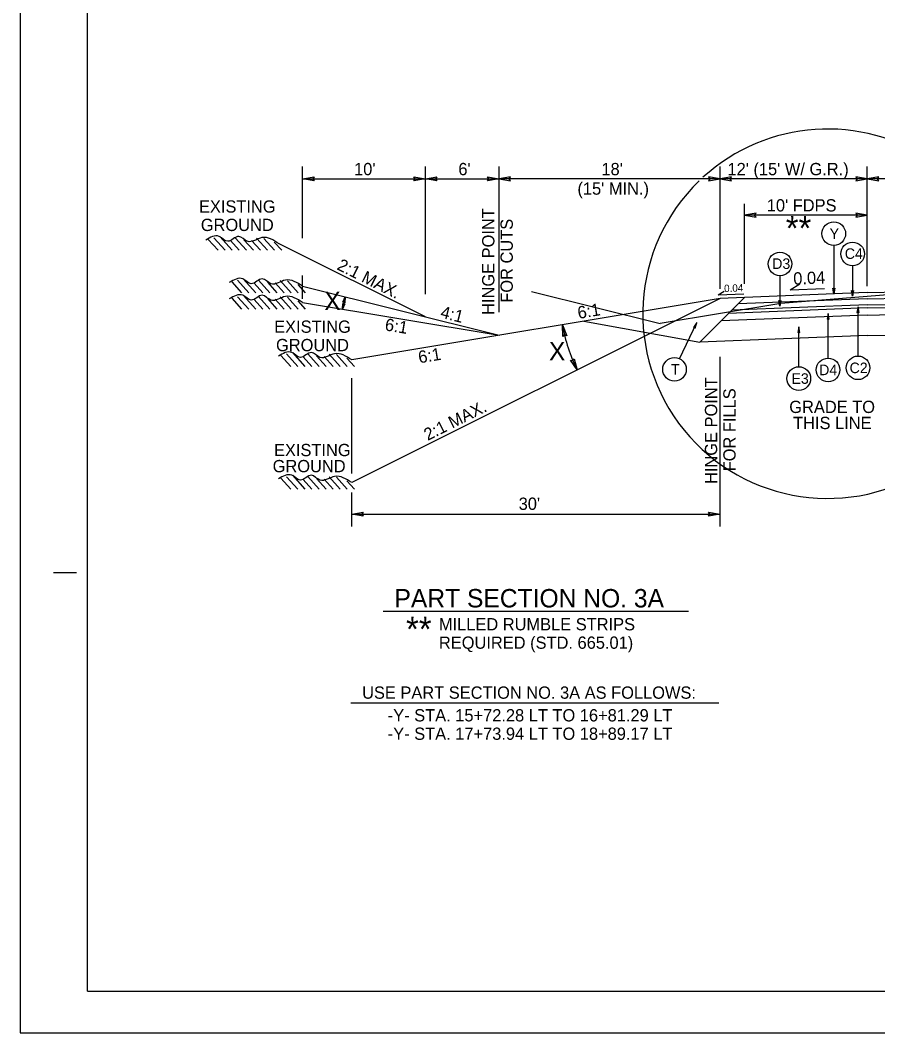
# Model space of a CAD drawing. Extents: x 1553884 to 1554215, y 810431 to 810779.
# Drawn here: x 1553901.4 to 1553971.2, y 810431 to 810513.5 of the extents above; entities that cross this region are included whole.
import ezdxf

# ---------------------------------------------------------------- set-up
doc = ezdxf.new("R2010")
doc.units = 0
for name, color, linetype in [('Old_Level_1', 7, 'Continuous'), ('Old_Level_15', 7, 'Continuous'), ('Old_Level_2', 7, 'Continuous'), ('Old_Level_20', 7, 'Continuous'), ('Prop Lane Arrow CELL', 7, 'Continuous'), ('Prop Shade Light', 7, 'Continuous'), ('Scratch_Level_0', 7, 'Continuous'), ('Sheet Plot Border Inside CELL', 7, 'Continuous'), ('Typical Arrow Superelevation CELL', 7, 'Continuous'), ('Typical Detail Pavement Repair CELL', 7, 'Continuous'), ('Typical Shoulder Slope CELL', 7, 'Continuous'), ('Typical Text ID Circle CELL', 7, 'Continuous')]:
    doc.layers.add(name, color=color, linetype=linetype)

msp = doc.modelspace()

# ---------------------------------------------------------------- linework, layer by layer
at = {"layer": 'Old_Level_1'}
for start, end in [(55.3594, 132.39727), (133.99022, 29.28511)]:
    msp.add_arc((1553967.115, 810489.54), 15.049, start, end, dxfattribs=at)
at = {"layer": 'Old_Level_15'}
for points in [[(1553925.295, 810500.365), (1553924.357, 810500.526), (1553925.3, 810500.693), (1553925.18, 810500.526)], [(1553933.42, 810500.688), (1553934.357, 810500.526), (1553933.415, 810500.36), (1553933.535, 810500.526)], [(1553935.295, 810500.365), (1553934.357, 810500.526), (1553935.3, 810500.693), (1553935.18, 810500.526)], [(1553939.42, 810500.688), (1553940.357, 810500.526), (1553939.415, 810500.36), (1553939.535, 810500.526)], [(1553941.295, 810500.688), (1553940.357, 810500.526), (1553941.3, 810500.36), (1553941.18, 810500.526)], [(1553957.42, 810500.365), (1553958.357, 810500.526), (1553957.415, 810500.693), (1553957.535, 810500.526)], [(1553959.295, 810500.688), (1553958.357, 810500.526), (1553959.3, 810500.36), (1553959.18, 810500.526)], [(1553969.42, 810500.365), (1553970.357, 810500.526), (1553969.415, 810500.693), (1553969.535, 810500.526)], [(1553971.295, 810500.688), (1553970.357, 810500.526), (1553971.3, 810500.36), (1553971.18, 810500.526)], [(1553961.295, 810497.732), (1553960.357, 810497.571), (1553961.3, 810497.404), (1553961.18, 810497.571)], [(1553969.42, 810497.409), (1553970.357, 810497.571), (1553969.415, 810497.737), (1553969.535, 810497.571)], [(1553927.64, 810490.475), (1553927.827, 810490.913), (1553927.799, 810490.435), (1553927.732, 810490.512)], [(1553967.705, 810491.619), (1553967.624, 810491.151), (1553967.541, 810491.622), (1553967.624, 810491.562)], [(1553969.236, 810491.435), (1553969.156, 810490.967), (1553969.072, 810491.438), (1553969.156, 810491.378)], [(1553927.781, 810490.35), (1553927.617, 810489.903), (1553927.62, 810490.382), (1553927.691, 810490.308)], [(1553963.324, 810490.618), (1553963.243, 810490.149), (1553963.16, 810490.62), (1553963.243, 810490.56)], [(1553969.68, 810489.63), (1553969.6, 810490.099), (1553969.516, 810489.627), (1553969.6, 810489.687)], [(1553967.24, 810489.095), (1553967.16, 810489.563), (1553967.076, 810489.092), (1553967.16, 810489.152)], [(1553945.546, 810487.69), (1553945.52, 810488.64), (1553945.869, 810487.749), (1553945.682, 810487.834)], [(1553956.341, 810488.357), (1553956.471, 810488.815), (1553956.192, 810488.425), (1553956.293, 810488.443)], [(1553964.857, 810488.009), (1553964.776, 810488.477), (1553964.693, 810488.006), (1553964.776, 810488.066)], [(1553946.471, 810485.878), (1553946.717, 810484.96), (1553946.171, 810485.746), (1553946.372, 810485.707)], [(1553929.295, 810473.053), (1553928.357, 810473.214), (1553929.3, 810473.381), (1553929.18, 810473.214)], [(1553957.42, 810473.376), (1553958.357, 810473.214), (1553957.415, 810473.048), (1553957.535, 810473.214)]]:
    msp.add_lwpolyline(points, close=True, dxfattribs=at)
at = {"layer": 'Old_Level_2'}
for p, q in [((1553906.821, 810434.329), (1553906.825, 810592.576)), ((1553904.055, 810468.454), (1553905.93, 810468.452)), ((1553906.821, 810434.329), (1554154.321, 810434.329))]:
    msp.add_line(p, q, dxfattribs=at)
at = {"layer": 'Old_Level_20'}
for p, q in [((1553942.992, 810491.361), (1553953.484, 810488.738)), ((1553972.357, 810491.1), (1553963.311, 810490.376)), ((1553963.311, 810490.376), (1553953.484, 810488.738))]:
    msp.add_line(p, q, dxfattribs=at)
at = {"layer": 'Prop Lane Arrow CELL'}
for p, q in [((1553901.353, 810595.951), (1553901.353, 810430.954)), ((1553901.353, 810430.954), (1554156.35, 810430.954))]:
    msp.add_line(p, q, dxfattribs=at)
at = {"layer": 'Prop Shade Light'}
for p, q in [((1553960.357, 810490.86), (1553956.711, 810487.214)), ((1553970.357, 810491.26), (1553960.357, 810490.86)), ((1553970.357, 810491.26), (1553982.357, 810491.5)), ((1553970.357, 810490.76), (1553982.357, 810491)), ((1553970.357, 810490.26), (1553959.316, 810489.818)), ((1553970.357, 810490.76), (1553959.836, 810490.339)), ((1553970.357, 810490.26), (1553972.357, 810490.3)), ((1553970.357, 810490.01), (1553972.357, 810490.05)), ((1553970.357, 810489.427), (1553958.448, 810488.95)), ((1553970.357, 810490.01), (1553959.055, 810489.558)), ((1553970.357, 810489.427), (1553972.357, 810489.467)), ((1553970.357, 810487.76), (1553956.711, 810487.214)), ((1553970.357, 810487.76), (1553972.357, 810487.8))]:
    msp.add_line(p, q, dxfattribs=at)
at = {"layer": 'Scratch_Level_0'}
msp.add_line((1553901.353, 810430.954), (1553901.353, 810430.954), dxfattribs=at)
at = {"layer": 'Sheet Plot Border Inside CELL'}
for p, q in [((1553917.599, 810495.845), (1553918.621, 810494.709)), ((1553916.672, 810495.596), (1553917.469, 810494.709)), ((1553917.134, 810495.722), (1553918.045, 810494.709)), ((1553918.487, 810495.498), (1553919.197, 810494.709)), ((1553918.848, 810495.737), (1553919.773, 810494.709)), ((1553919.573, 810495.571), (1553920.349, 810494.709)), ((1553920.197, 810495.519), (1553920.925, 810494.709)), ((1553920.607, 810495.703), (1553921.501, 810494.709)), ((1553921.202, 810495.681), (1553922.077, 810494.709)), ((1553922.051, 810495.378), (1553922.653, 810494.709)), ((1553918.59, 810492.136), (1553919.388, 810491.25)), ((1553919.053, 810492.262), (1553919.964, 810491.25)), ((1553919.518, 810492.385), (1553920.54, 810491.25)), ((1553920.406, 810492.039), (1553921.116, 810491.25)), ((1553920.767, 810492.278), (1553921.692, 810491.25)), ((1553921.492, 810492.112), (1553922.268, 810491.25)), ((1553922.116, 810492.059), (1553922.844, 810491.25)), ((1553922.526, 810492.244), (1553923.42, 810491.25)), ((1553923.121, 810492.222), (1553923.996, 810491.25)), ((1553923.97, 810491.918), (1553924.572, 810491.25)), ((1553919.053, 810490.929), (1553919.964, 810489.916)), ((1553919.518, 810491.052), (1553920.54, 810489.916)), ((1553920.767, 810490.945), (1553921.692, 810489.916)), ((1553922.526, 810490.91), (1553923.42, 810489.916)), ((1553923.121, 810490.889), (1553923.996, 810489.916)), ((1553918.59, 810490.803), (1553919.388, 810489.916)), ((1553920.406, 810490.706), (1553921.116, 810489.916)), ((1553921.492, 810490.779), (1553922.268, 810489.916)), ((1553922.116, 810490.726), (1553922.844, 810489.916)), ((1553923.97, 810490.585), (1553924.572, 810489.916)), ((1553922.59, 810486.136), (1553923.388, 810485.25)), ((1553923.053, 810486.262), (1553923.964, 810485.25)), ((1553923.518, 810486.385), (1553924.54, 810485.25)), ((1553924.406, 810486.039), (1553925.116, 810485.25)), ((1553924.767, 810486.278), (1553925.692, 810485.25)), ((1553925.492, 810486.112), (1553926.268, 810485.25)), ((1553926.116, 810486.059), (1553926.844, 810485.25)), ((1553926.526, 810486.244), (1553927.42, 810485.25)), ((1553927.121, 810486.222), (1553927.996, 810485.25)), ((1553927.97, 810485.918), (1553928.572, 810485.25)), ((1553922.59, 810476.136), (1553923.388, 810475.25)), ((1553923.053, 810476.262), (1553923.964, 810475.25)), ((1553923.518, 810476.385), (1553924.54, 810475.25)), ((1553924.406, 810476.039), (1553925.116, 810475.25)), ((1553924.767, 810476.278), (1553925.692, 810475.25)), ((1553925.492, 810476.112), (1553926.268, 810475.25)), ((1553926.116, 810476.059), (1553926.844, 810475.25)), ((1553926.526, 810476.244), (1553927.42, 810475.25)), ((1553927.121, 810476.222), (1553927.996, 810475.25)), ((1553927.97, 810475.918), (1553928.572, 810475.25))]:
    msp.add_line(p, q, dxfattribs=at)
for points in [[(1553922.438, 810495.239), (1553921.044, 810495.738), (1553919.849, 810495.439), (1553919.152, 810495.838), (1553918.256, 810495.439), (1553917.558, 810495.838), (1553916.463, 810495.539)], [(1553924.357, 810491.78), (1553922.963, 810492.279), (1553921.768, 810491.979), (1553921.071, 810492.378), (1553920.175, 810491.979), (1553919.477, 810492.378), (1553918.382, 810492.079)], [(1553924.357, 810490.447), (1553922.963, 810490.945), (1553921.768, 810490.646), (1553921.071, 810491.045), (1553920.175, 810490.646), (1553919.477, 810491.045), (1553918.382, 810490.746)], [(1553928.357, 810485.78), (1553926.963, 810486.279), (1553925.768, 810485.979), (1553925.071, 810486.378), (1553924.175, 810485.979), (1553923.477, 810486.378), (1553922.382, 810486.079)], [(1553928.357, 810475.78), (1553926.963, 810476.279), (1553925.768, 810475.979), (1553925.071, 810476.378), (1553924.175, 810475.979), (1553923.477, 810476.378), (1553922.382, 810476.079)]]:
    msp.add_spline(points, degree=3, dxfattribs=at)
at = {"layer": 'Typical Arrow Superelevation CELL'}
for p, q in [((1553940.357, 810489.66), (1553940.357, 810501.526)), ((1553958.357, 810491.557), (1553958.357, 810501.526)), ((1553960.357, 810491.975), (1553960.357, 810498.485)), ((1553964.076, 810491.477), (1553964.85, 810491.966)), ((1553958.218, 810491.075), (1553958.682, 810491.368)), ((1553958.218, 810491.075), (1553960.288, 810491.157)), ((1553964.076, 810491.477), (1553966.871, 810491.589)), ((1553958.357, 810472.214), (1553958.357, 810486.035)), ((1553928.357, 810476.524), (1553928.357, 810484.301)), ((1553928.357, 810472.214), (1553928.357, 810474.97)), ((1553930.921, 810465.301), (1553955.794, 810465.301)), ((1553928.296, 810457.849), (1553958.255, 810457.849))]:
    msp.add_line(p, q, dxfattribs=at)
for centre, radius, start, end in [((1553940.357, 810487.78), 12.916, 165.96376, 170.53768), ((1553958.357, 810490.78), 13.014, 189.46232, 206.56505)]:
    msp.add_arc(centre, radius, start, end, dxfattribs=at)
at = {"layer": 'Typical Shoulder Slope CELL'}
for p, q in [((1553924.357, 810495.694), (1553924.357, 810501.526)), ((1553934.357, 810491.147), (1553934.357, 810501.526)), ((1553970.357, 810491.78), (1553970.357, 810501.526)), ((1553924.357, 810500.526), (1553934.357, 810500.526)), ((1553934.357, 810500.526), (1553940.357, 810500.526)), ((1553958.357, 810500.526), (1553940.357, 810500.526)), ((1553970.357, 810500.526), (1553958.357, 810500.526)), ((1553982.357, 810500.526), (1553970.357, 810500.526)), ((1553970.357, 810497.571), (1553960.357, 810497.571)), ((1553934.357, 810489.28), (1553922.438, 810495.239)), ((1553924.357, 810490.755), (1553924.357, 810492.646)), ((1553924.357, 810491.78), (1553940.357, 810487.78)), ((1553960.357, 810490.86), (1553958.357, 810490.78)), ((1553924.357, 810490.447), (1553940.357, 810487.78)), ((1553958.357, 810490.78), (1553928.357, 810485.78)), ((1553958.357, 810490.78), (1553928.357, 810475.78)), ((1553947.263, 810488.931), (1553956.711, 810487.214)), ((1553928.357, 810473.214), (1553958.357, 810473.214))]:
    msp.add_line(p, q, dxfattribs=at)
at = {"layer": 'Typical Text ID Circle CELL'}
for p, q in [((1553967.624, 810495.103), (1553967.624, 810491.151)), ((1553969.156, 810493.452), (1553969.156, 810490.967)), ((1553963.243, 810492.634), (1553963.243, 810490.149)), ((1553969.6, 810486.091), (1553969.6, 810490.099)), ((1553967.16, 810485.924), (1553967.16, 810489.563)), ((1553955.066, 810485.875), (1553956.471, 810488.815)), ((1553964.776, 810485.219), (1553964.776, 810488.477))]:
    msp.add_line(p, q, dxfattribs=at)
for centre in [(1553967.624, 810496.064), (1553969.156, 810494.413), (1553963.243, 810493.596), (1553954.651, 810485.007), (1553967.16, 810484.962), (1553969.6, 810485.13), (1553964.776, 810484.258)]:
    msp.add_circle(centre, 0.962, dxfattribs=at)

# ---------------------------------------------------------------- texts
at = {"layer": 'Typical Arrow Superelevation CELL'}
for s, height, p in [("10'", 1, (1553928.547, 810500.827)), ("6'", 1, (1553937.042, 810500.827)), ("18'", 1, (1553948.697, 810500.827)), ("12' (15' W/ G.R.)", 1, (1553958.966, 810500.827)), ("(15' MIN.)", 1, (1553946.743, 810499.239)), ('EXISTING', 1, (1553915.912, 810497.778)), ("10' FDPS", 1, (1553962.166, 810497.871)), ('**', 2, (1553963.715, 810495.508)), ('GROUND', 1, (1553916.061, 810496.278)), ('X', 1.5, (1553926.118, 810489.837)), ('EXISTING', 1, (1553922.039, 810487.986)), ('GROUND', 1, (1553922.188, 810486.486)), ('X', 1.5, (1553944.421, 810485.733)), ('GRADE TO ', 1, (1553963.999, 810481.45)), ('THIS LINE', 1, (1553964.311, 810480.139)), ('EXISTING', 1, (1553922.025, 810477.935)), ('GROUND', 1, (1553921.916, 810476.624)), ("30'", 1, (1553941.956, 810473.559)), ('PART SECTION NO. 3A', 1.5, (1553931.838, 810465.609)), ('**', 2, (1553932.779, 810462.843)), ('MILLED RUMBLE STRIPS', 1, (1553935.458, 810463.74)), ('REQUIRED (STD. 665.01)', 1, (1553935.458, 810462.24)), ('USE PART SECTION NO. 3A AS FOLLOWS:', 1, (1553929.202, 810458.169)), ('-Y- STA. 15+72.28 LT TO 16+81.29 LT', 1, (1553931.291, 810456.321)), ('-Y- STA. 17+73.94 LT TO 18+89.17 LT', 1, (1553931.291, 810454.821))]:
    msp.add_text(s, height=height, dxfattribs=at).set_placement(p)
for s, height, rotation, p in [('HINGE POINT', 1, 90, (1553939.978, 810489.445)), ('FOR CUTS', 1, 90, (1553941.478, 810490.438)), ('2:1 MAX.', 1, 333.43495, (1553927.079, 810493.184)), ('0.04', 1, 2.29061, (1553964.345, 810491.906)), ('0.04', 0.6, 2.29061, (1553958.702, 810491.299)), ('4:1', 1, 345.96376, (1553935.52, 810489.23)), ('6:1', 1, 9.46232, (1553946.835, 810489.116)), ('6:1', 1, 350.53768, (1553931.005, 810488.194)), ('6:1', 1, 9.46232, (1553933.862, 810485.494)), ('HINGE POINT', 1, 90, (1553958.127, 810475.666)), ('FOR FILLS', 1, 90, (1553959.627, 810476.698)), ('2:1 MAX.', 1, 26.56505, (1553934.544, 810479.168))]:
    msp.add_text(s, height=height, rotation=rotation, dxfattribs=at).set_placement(p)
at = {"layer": 'Typical Detail Pavement Repair CELL'}
for s, height, p in [('Y', 0.861, (1553967.287, 810495.634)), ('C4', 0.8608, (1553968.52, 810494.007)), ('D3', 0.8608, (1553962.609, 810493.189)), ('T', 0.861, (1553954.368, 810484.577)), ('D4', 0.8608, (1553966.433, 810484.532)), ('C2', 0.8608, (1553968.914, 810484.699)), ('E3', 0.8608, (1553964.18, 810483.827))]:
    msp.add_text(s, height=height, dxfattribs=at).set_placement(p)

doc.saveas('drawing.dxf')
